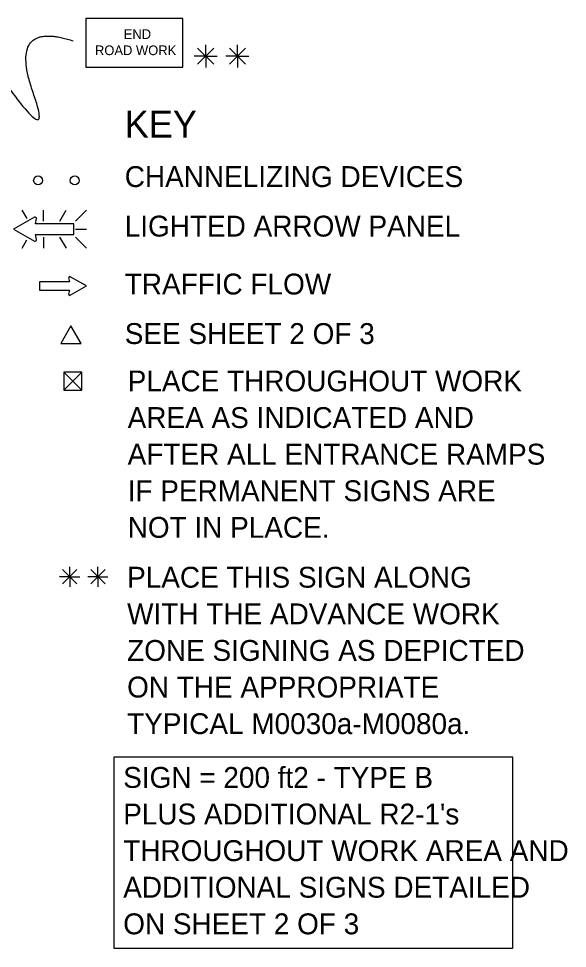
# Model space of a CAD drawing. Extents: x 16604 to 19504, y 6997 to 8305.
# Drawn here: x 17198.4 to 17442.7, y 7602 to 8016 of the extents above; entities that cross this region are included whole.
import ezdxf

# ---------------------------------------------------------------- set-up
doc = ezdxf.new("R2010")
doc.units = 0
for name, color, linetype in [('MT_SCRATCH_LEVEL_E', 7, 'Continuous'), ('TRAFFIC_SIGNS_PR', 7, 'Continuous'), ('TYPICAL_TEXT_DIMEN_EX', 7, 'Continuous'), ('TYPICAL_TEXT_DIMEN_PR', 7, 'Continuous')]:
    doc.layers.add(name, color=color, linetype=linetype)

msp = doc.modelspace()

# ---------------------------------------------------------------- linework, layer by layer
at = {"layer": 'MT_SCRATCH_LEVEL_E'}
for p, q in [((17220.7, 7900.6), (17221.01, 7898.82)), ((17228.62, 7896.97), (17221.39, 7901.08)), ((17221.01, 7898.82), (17207.76, 7898.82)), ((17207.76, 7898.82), (17207.76, 7895.08)), ((17221.39, 7892.82), (17228.62, 7896.97)), ((17207.76, 7895.08), (17221.01, 7895.08)), ((17221.01, 7895.08), (17220.7, 7893.3))]:
    msp.add_line(p, q, dxfattribs=at)
for centre, start, end in [((17221.16, 7900.67), 60.4248, 189.9638), ((17221.16, 7893.23), 170.0362, 299.7731)]:
    msp.add_arc(centre, 0.463, start, end, dxfattribs=at)
at = {"layer": 'TRAFFIC_SIGNS_PR'}
for p, q in [((17202.24, 7926.95), (17200.03, 7930.78)), ((17209.56, 7925.84), (17209.56, 7930.78)), ((17216.79, 7925.84), (17219.64, 7930.78)), ((17223.71, 7925.84), (17228.64, 7930.78)), ((17223.71, 7922.29), (17228.64, 7922.29)), ((17199.99, 7913.8), (17202.1, 7917.46)), ((17209.56, 7918.73), (17209.56, 7913.8)), ((17219.69, 7913.8), (17216.84, 7918.73)), ((17223.71, 7918.73), (17228.64, 7913.8))]:
    msp.add_line(p, q, dxfattribs=at)
msp.add_lwpolyline([(17228.35, 7994.45), (17271.55, 7994.45), (17271.55, 8016.05), (17228.35, 8016.05)], close=True, dxfattribs=at)
for points in [[(17205.49, 7927.56), (17196.19, 7922.29), (17205.49, 7916.97)], [(17206.36, 7917.6), (17205.96, 7919.86), (17222.97, 7919.86), (17222.97, 7924.66), (17205.96, 7924.66), (17206.36, 7926.95)]]:
    msp.add_lwpolyline(points, dxfattribs=at)
for centre in [(17207.12, 7943.97), (17223.42, 7943.97)]:
    msp.add_circle(centre, 2, dxfattribs=at)
for centre, radius, start, end in [((17205.77, 7927.04), 0.598, 350.7308, 118.8916), ((17205.77, 7917.49), 0.597, 241.4833, 9.9593)]:
    msp.add_arc(centre, radius, start, end, dxfattribs=at)
at = {"layer": 'TYPICAL_TEXT_DIMEN_EX'}
msp.add_lwpolyline([(17240.92, 7687.29), (17418.2, 7687.29), (17418.2, 7601.97), (17240.92, 7601.97)], close=True, dxfattribs=at)
at = {"layer": 'TYPICAL_TEXT_DIMEN_PR'}
for p, q in [((17281.7, 7999.37), (17281.7, 8004.38)), ((17295.82, 7999.37), (17295.82, 8004.38)), ((17278.11, 8002.95), (17285.28, 7995.78)), ((17285.28, 8002.95), (17278.11, 7995.78)), ((17292.24, 8002.95), (17299.41, 7995.78)), ((17299.41, 8002.95), (17292.24, 7995.78)), ((17281.7, 7999.37), (17276.6, 7999.37)), ((17281.7, 7999.37), (17285.28, 7999.37)), ((17281.7, 7999.37), (17286.73, 7999.37)), ((17281.7, 7999.37), (17281.7, 7994.3)), ((17295.82, 7999.37), (17290.72, 7999.37)), ((17295.82, 7999.37), (17299.41, 7999.37)), ((17295.82, 7999.37), (17300.86, 7999.37)), ((17295.82, 7999.37), (17295.82, 7994.3)), ((17218.58, 7858.61), (17226.58, 7850.61)), ((17218.58, 7850.61), (17226.58, 7858.61)), ((17217.97, 7770.67), (17224.34, 7764.29)), ((17224.34, 7770.67), (17217.97, 7764.29)), ((17221.15, 7767.48), (17221.15, 7771.94)), ((17230.52, 7770.67), (17236.9, 7764.29)), ((17236.9, 7770.67), (17230.52, 7764.29)), ((17233.71, 7767.48), (17233.71, 7771.94)), ((17221.15, 7767.48), (17216.62, 7767.48)), ((17221.15, 7767.48), (17224.34, 7767.48)), ((17221.15, 7767.48), (17225.63, 7767.48)), ((17221.15, 7767.48), (17221.15, 7762.98)), ((17233.71, 7767.48), (17229.18, 7767.48)), ((17233.71, 7767.48), (17236.9, 7767.48)), ((17233.71, 7767.48), (17238.19, 7767.48)), ((17233.71, 7767.48), (17233.71, 7762.98))]:
    msp.add_line(p, q, dxfattribs=at)
for points in [[(17221.69, 7879.26), (17217.17, 7871.42), (17226.22, 7871.42)], [(17218.58, 7858.61), (17218.58, 7850.61), (17226.58, 7850.61), (17226.58, 7858.61)]]:
    msp.add_lwpolyline(points, close=True, dxfattribs=at)
msp.add_open_spline([(17178.35, 8008.18), (17216.58, 7950.01), (17193.37, 8015.71), (17222.72, 8006.13)], degree=2, dxfattribs=at)

# ---------------------------------------------------------------- texts
at = {"layer": 'TRAFFIC_SIGNS_PR'}
for s, p in [('END', (17245.22, 8006.97)), ('ROAD WORK', (17232.41, 7999.78))]:
    msp.add_text(s, height=4.31, dxfattribs=at).set_placement(p)
at = {"layer": 'TYPICAL_TEXT_DIMEN_EX'}
for s, height, p in [('KEY', 12, (17245.66, 7963.08)), ('CHANNELIZING DEVICES', 9.3, (17245.66, 7941.03)), ('LIGHTED ARROW PANEL', 9.3, (17245.66, 7918.98)), ('TRAFFIC FLOW', 9.3, (17245.66, 7893.18)), ('SEE SHEET 2 OF 3', 9.3, (17245.66, 7871.13)), ('PLACE THROUGHOUT WORK', 9.3, (17246.97, 7850.02)), ('AREA AS INDICATED AND', 9.3, (17246.97, 7833.72)), ('AFTER ALL ENTRANCE RAMPS', 9.3, (17246.97, 7817.42)), ('IF PERMANENT SIGNS ARE', 9.3, (17246.97, 7801.12)), ('NOT IN PLACE.', 9.3, (17246.97, 7784.82)), ('PLACE THIS SIGN ALONG', 9.3, (17246.72, 7762.61)), ('WITH THE ADVANCE WORK', 9.3, (17246.72, 7746.31)), ('ZONE SIGNING AS DEPICTED', 9.3, (17246.72, 7730.01)), ('ON THE APPROPRIATE', 9.3, (17246.72, 7713.71)), ('TYPICAL M0030a-M0080a.', 9.3, (17246.72, 7697.41)), ('SIGN = 200 ft2 - TYPE B', 9.3, (17244.98, 7673.46)), ("PLUS ADDITIONAL R2-1's", 9.3, (17244.98, 7657.16)), ('THROUGHOUT WORK AREA AND', 9.3, (17244.98, 7640.86)), ('ADDITIONAL SIGNS DETAILED', 9.3, (17244.98, 7624.56)), ('ON SHEET 2 OF 3', 9.3, (17244.98, 7608.26))]:
    msp.add_text(s, height=height, dxfattribs=at).set_placement(p)

doc.saveas('drawing.dxf')
